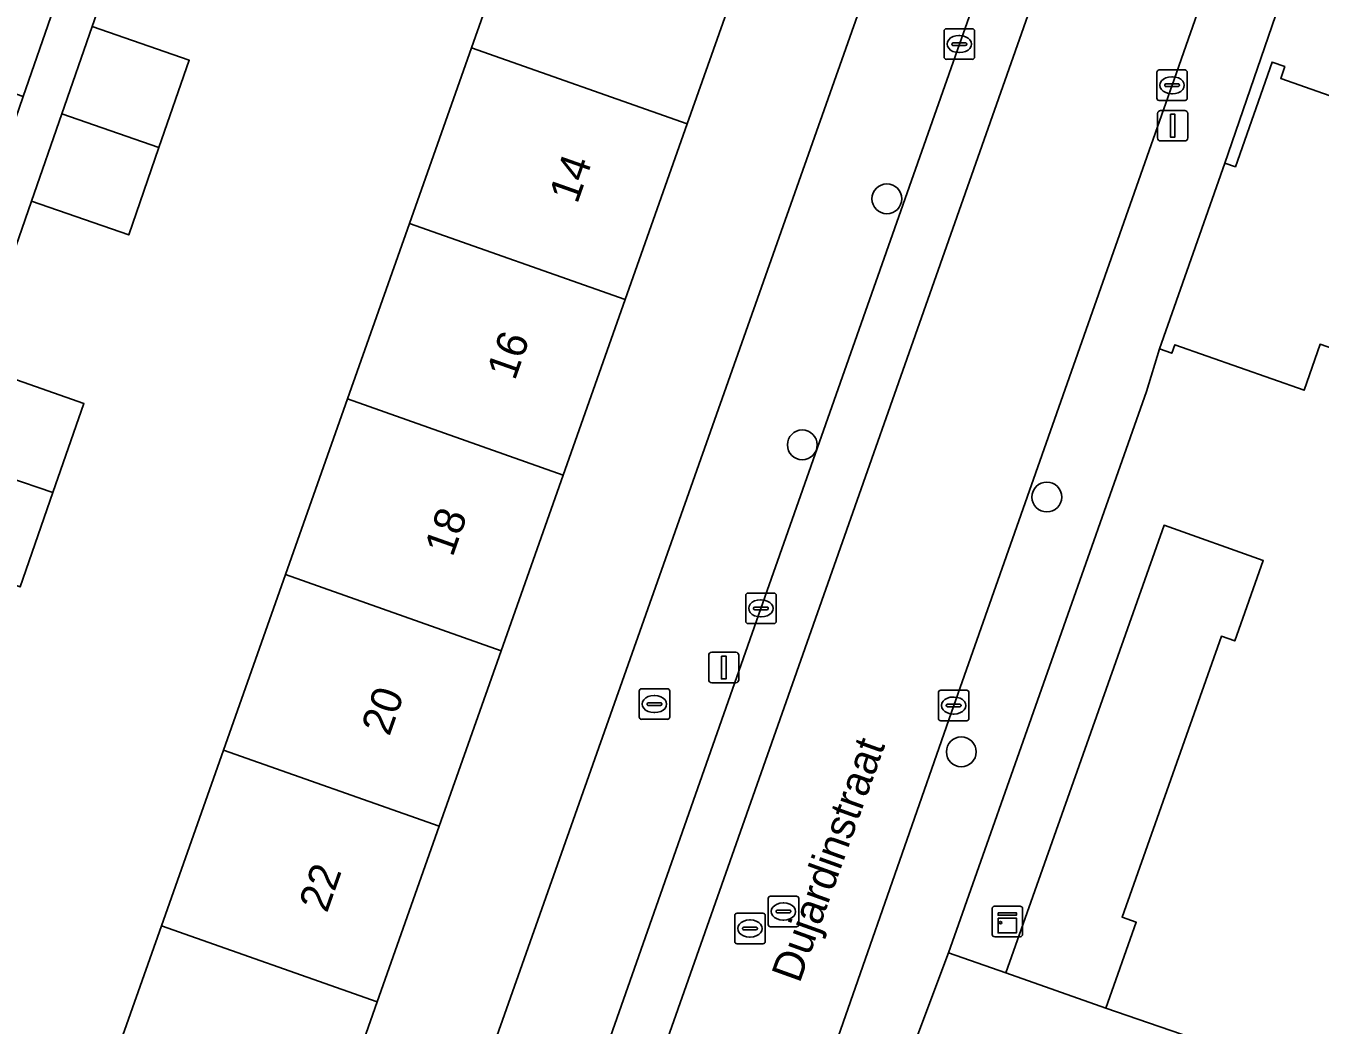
# Model space of a CAD drawing. Extents: x 163266 to 164362, y 381528 to 382286.
# Drawn here: x 163762.33 to 163804.78, y 381920.09 to 381952.84 of the extents above; entities that cross this region are included whole.
import ezdxf

# ---------------------------------------------------------------- set-up
doc = ezdxf.new("R2010")
doc.units = 0
for name, color, linetype in [('IMGEO_Boom', 7, 'Continuous'), ('IMGEO_Brandkraan', 7, 'Continuous'), ('IMGEO_Erf', 7, 'Continuous'), ('IMGEO_Kast', 7, 'Continuous'), ('IMGEO_Kolk', 7, 'Continuous'), ('IMGEO_Lichtmast', 7, 'Continuous'), ('IMGEO_Openbare_ruimte_label', 7, 'Continuous'), ('IMGEO_Pand', 7, 'Continuous'), ('IMGEO_Pand_nummerreeks', 7, 'Continuous'), ('IMGEO_Parkeervlak_open', 7, 'Continuous'), ('IMGEO_Rijbaan_lokaal_open', 7, 'Continuous'), ('IMGEO_Rioolput', 7, 'Continuous'), ('IMGEO_Voetpad_open', 7, 'Continuous')]:
    doc.layers.add(name, color=color, linetype=linetype)

msp = doc.modelspace()

# ---------------------------------------------------------------- linework, layer by layer
at = {"layer": 'IMGEO_Boom'}
for centre in [(163790.573, 381947.177), (163787.797, 381939.109), (163795.82, 381937.4), (163793.013, 381929.046)]:
    msp.add_circle(centre, 0.489, dxfattribs=at)
at = {"layer": 'IMGEO_Brandkraan'}
for p, q in [((163782.446, 381930.187), (163782.446, 381931.039)), ((163782.521, 381931.113), (163783.373, 381931.113)), ((163782.934, 381930.893), (163782.959, 381930.893)), ((163783.447, 381931.039), (163783.447, 381930.187)), ((163782.705, 381930.607), (163782.705, 381930.619)), ((163783.143, 381930.57), (163782.745, 381930.57)), ((163782.748, 381930.656), (163783.146, 381930.656)), ((163782.957, 381930.333), (163782.932, 381930.333)), ((163783.189, 381930.619), (163783.189, 381930.607)), ((163783.373, 381930.113), (163782.521, 381930.113))]:
    msp.add_line(p, q, dxfattribs=at)
for points in [[(163782.446, 381930.187), (163782.446, 381931.039)], [(163782.521, 381931.113), (163783.373, 381931.113)], [(163783.447, 381931.039), (163783.447, 381930.187)], [(163783.373, 381930.113), (163782.521, 381930.113)]]:
    msp.add_lwpolyline(points, dxfattribs=at)
for centre, radius, start, end in [((163782.523, 381931.037), 0.0765, 91.552, 178.448), ((163782.523, 381931.037), 0.0765, 91.552, 178.448), ((163783.371, 381931.037), 0.0765, 1.552, 88.448), ((163783.371, 381931.037), 0.0765, 1.552, 88.448), ((163782.745, 381930.616), 0.0403, 85.8775, 175.7526), ((163782.742, 381930.606), 0.0366, 178.938, 274.7102), ((163783.146, 381930.613), 0.043, 264.8664, 352.4533), ((163783.15, 381930.618), 0.0386, 1.7309, 96.639), ((163782.523, 381930.189), 0.0765, 181.552, 268.448), ((163782.523, 381930.189), 0.0765, 181.552, 268.448), ((163783.371, 381930.189), 0.0765, 271.552, 358.448), ((163783.371, 381930.189), 0.0765, 271.552, 358.448)]:
    msp.add_arc(centre, radius, start, end, dxfattribs=at)
for centre, major_axis, ratio, start_param, end_param in [((163782.933, 381930.613), (-0.387, 0.002), 0.722429, 4.712389, 7.853982), ((163782.958, 381930.613), (-0.39, 0.002), 0.717154, 1.570796, 4.712389)]:
    msp.add_ellipse(centre, major_axis=major_axis, ratio=ratio, start_param=start_param, end_param=end_param, dxfattribs=at)
at = {"layer": 'IMGEO_Erf'}
msp.add_lwpolyline([(163791.996, 381959.944), (163788.141, 381961.307), (163786.05, 381955.385), (163784.018, 381949.629), (163781.986, 381943.873), (163779.953, 381938.117), (163777.921, 381932.362), (163775.889, 381926.606), (163773.857, 381920.85), (163771.824, 381915.094), (163769.792, 381909.339), (163767.703, 381903.421), (163771.539, 381902.067)], close=True, dxfattribs=at)
for points in [[(163766.535, 381958.634), (163764.506, 381952.826), (163767.69, 381951.72), (163766.695, 381948.856), (163765.701, 381945.992), (163762.517, 381947.097), (163760.643, 381941.721), (163764.235, 381940.469), (163763.218, 381937.553), (163762.137, 381934.452)], [(163760.627, 381905.919), (163762.717, 381911.837), (163764.749, 381917.592), (163766.781, 381923.348), (163768.814, 381929.105), (163770.846, 381934.861), (163772.878, 381940.616), (163774.911, 381946.372), (163776.943, 381952.128), (163778.975, 381957.883)], [(163804.785, 381942.408), (163804.255, 381940.9), (163800.015, 381942.39), (163799.918, 381942.116), (163799.514, 381942.258), (163799.091, 381940.863), (163792.59, 381922.456), (163794.479, 381921.807), (163799.663, 381936.474), (163802.92, 381935.323), (163801.986, 381932.681), (163801.545, 381932.837), (163798.288, 381923.623), (163798.75, 381923.459), (163797.756, 381920.649), (163820.697, 381912.77)]]:
    msp.add_lwpolyline(points, dxfattribs=at)
at = {"layer": 'IMGEO_Kast'}
for p, q in [((163794.099, 381923.984), (163794.94, 381923.984)), ((163794.94, 381923.984), (163794.099, 381923.984)), ((163794.024, 381923.059), (163794.024, 381923.9)), ((163794.024, 381923.9), (163794.024, 381923.059)), ((163795.024, 381923.909), (163795.024, 381923.068)), ((163795.024, 381923.068), (163795.024, 381923.909)), ((163794.949, 381922.984), (163794.108, 381922.984)), ((163794.108, 381922.984), (163794.949, 381922.984))]:
    msp.add_line(p, q, dxfattribs=at)
for points in [[(163794.219, 381923.774), (163794.819, 381923.774), (163794.819, 381923.689), (163794.219, 381923.689), (163794.219, 381923.774)], [(163794.219, 381923.599), (163794.819, 381923.599), (163794.819, 381923.11), (163794.219, 381923.11), (163794.219, 381923.599)]]:
    msp.add_lwpolyline(points, dxfattribs=at)
msp.add_circle((163794.303, 381923.448), 0.0377, dxfattribs=at)
for centre, start, end in [((163794.102, 381923.906), 92.4484, 184.2845), ((163794.102, 381923.906), 92.4484, 184.2845), ((163794.946, 381923.906), 2.4484, 94.2845), ((163794.946, 381923.906), 2.4484, 94.2845), ((163794.102, 381923.062), 182.4484, 274.2845), ((163794.102, 381923.062), 182.4484, 274.2845), ((163794.946, 381923.062), 272.4484, 4.2845), ((163794.946, 381923.062), 272.4484, 4.2845)]:
    msp.add_arc(centre, 0.0779, start, end, dxfattribs=at)
at = {"layer": 'IMGEO_Kolk'}
for p, q in [((163792.448, 381951.823), (163792.448, 381952.675)), ((163792.523, 381952.749), (163793.375, 381952.749)), ((163792.936, 381952.529), (163792.961, 381952.529)), ((163793.449, 381952.675), (163793.449, 381951.823)), ((163792.707, 381952.243), (163792.707, 381952.255)), ((163793.145, 381952.206), (163792.747, 381952.206)), ((163792.75, 381952.292), (163793.148, 381952.292)), ((163792.959, 381951.969), (163792.934, 381951.969)), ((163793.191, 381952.255), (163793.191, 381952.243)), ((163793.375, 381951.749), (163792.523, 381951.749)), ((163799.426, 381950.473), (163799.426, 381951.325)), ((163799.501, 381951.399), (163800.353, 381951.399)), ((163799.914, 381951.179), (163799.939, 381951.179)), ((163800.427, 381951.325), (163800.427, 381950.473)), ((163799.685, 381950.893), (163799.685, 381950.905)), ((163800.123, 381950.856), (163799.725, 381950.856)), ((163799.728, 381950.942), (163800.126, 381950.942)), ((163800.169, 381950.905), (163800.169, 381950.893)), ((163800.353, 381950.399), (163799.501, 381950.399)), ((163799.937, 381950.619), (163799.912, 381950.619)), ((163785.94, 381933.324), (163785.94, 381934.176)), ((163786.015, 381934.25), (163786.867, 381934.25)), ((163786.941, 381934.176), (163786.941, 381933.324)), ((163786.199, 381933.744), (163786.199, 381933.756)), ((163786.637, 381933.707), (163786.239, 381933.707)), ((163786.242, 381933.793), (163786.64, 381933.793)), ((163786.428, 381934.03), (163786.453, 381934.03)), ((163786.683, 381933.756), (163786.683, 381933.744)), ((163786.451, 381933.47), (163786.426, 381933.47)), ((163786.867, 381933.25), (163786.015, 381933.25)), ((163792.263, 381930.138), (163792.263, 381930.99)), ((163792.338, 381931.064), (163793.19, 381931.064)), ((163792.751, 381930.844), (163792.776, 381930.844)), ((163793.264, 381930.99), (163793.264, 381930.138)), ((163792.522, 381930.558), (163792.522, 381930.57)), ((163792.96, 381930.521), (163792.562, 381930.521)), ((163792.565, 381930.607), (163792.963, 381930.607)), ((163793.006, 381930.57), (163793.006, 381930.558)), ((163793.19, 381930.064), (163792.338, 381930.064)), ((163792.774, 381930.284), (163792.749, 381930.284))]:
    msp.add_line(p, q, dxfattribs=at)
for points in [[(163792.448, 381951.823), (163792.448, 381952.675)], [(163792.523, 381952.749), (163793.375, 381952.749)], [(163793.449, 381952.675), (163793.449, 381951.823)], [(163793.375, 381951.749), (163792.523, 381951.749)], [(163799.426, 381950.473), (163799.426, 381951.325)], [(163799.501, 381951.399), (163800.353, 381951.399)], [(163800.427, 381951.325), (163800.427, 381950.473)], [(163800.353, 381950.399), (163799.501, 381950.399)], [(163785.94, 381933.324), (163785.94, 381934.176)], [(163786.015, 381934.25), (163786.867, 381934.25)], [(163786.941, 381934.176), (163786.941, 381933.324)], [(163786.867, 381933.25), (163786.015, 381933.25)], [(163792.263, 381930.138), (163792.263, 381930.99)], [(163792.338, 381931.064), (163793.19, 381931.064)], [(163793.264, 381930.99), (163793.264, 381930.138)], [(163793.19, 381930.064), (163792.338, 381930.064)]]:
    msp.add_lwpolyline(points, dxfattribs=at)
for centre, radius, start, end in [((163792.525, 381952.673), 0.0765, 91.552, 178.448), ((163792.525, 381952.673), 0.0765, 91.552, 178.448), ((163793.373, 381952.673), 0.0765, 1.552, 88.448), ((163793.373, 381952.673), 0.0765, 1.552, 88.448), ((163792.747, 381952.252), 0.0403, 85.8775, 175.7526), ((163792.744, 381952.242), 0.0366, 178.938, 274.7102), ((163793.148, 381952.249), 0.043, 264.8664, 352.4533), ((163793.152, 381952.254), 0.0386, 1.7309, 96.639), ((163792.525, 381951.825), 0.0765, 181.552, 268.448), ((163792.525, 381951.825), 0.0765, 181.552, 268.448), ((163793.373, 381951.825), 0.0765, 271.552, 358.448), ((163793.373, 381951.825), 0.0765, 271.552, 358.448), ((163799.503, 381951.323), 0.0765, 91.552, 178.448), ((163799.503, 381951.323), 0.0765, 91.552, 178.448), ((163800.351, 381951.323), 0.0765, 1.552, 88.448), ((163800.351, 381951.323), 0.0765, 1.552, 88.448), ((163799.725, 381950.902), 0.0403, 85.8775, 175.7526), ((163799.722, 381950.892), 0.0366, 178.938, 274.7102), ((163800.126, 381950.899), 0.043, 264.8664, 352.4533), ((163800.13, 381950.904), 0.0386, 1.7309, 96.639), ((163799.503, 381950.475), 0.0765, 181.552, 268.448), ((163799.503, 381950.475), 0.0765, 181.552, 268.448), ((163800.351, 381950.475), 0.0765, 271.552, 358.448), ((163800.351, 381950.475), 0.0765, 271.552, 358.448), ((163786.017, 381934.174), 0.0765, 91.552, 178.448), ((163786.017, 381934.174), 0.0765, 91.552, 178.448), ((163786.865, 381934.174), 0.0765, 1.552, 88.448), ((163786.865, 381934.174), 0.0765, 1.552, 88.448), ((163786.239, 381933.753), 0.0403, 85.8775, 175.7526), ((163786.236, 381933.743), 0.0366, 178.938, 274.7102), ((163786.64, 381933.75), 0.043, 264.8664, 352.4533), ((163786.644, 381933.755), 0.0386, 1.7309, 96.639), ((163786.017, 381933.326), 0.0765, 181.552, 268.448), ((163786.017, 381933.326), 0.0765, 181.552, 268.448), ((163786.865, 381933.326), 0.0765, 271.552, 358.448), ((163786.865, 381933.326), 0.0765, 271.552, 358.448), ((163792.34, 381930.988), 0.0765, 91.552, 178.448), ((163792.34, 381930.988), 0.0765, 91.552, 178.448), ((163793.188, 381930.988), 0.0765, 1.552, 88.448), ((163793.188, 381930.988), 0.0765, 1.552, 88.448), ((163792.562, 381930.567), 0.0403, 85.8775, 175.7526), ((163792.559, 381930.557), 0.0366, 178.938, 274.7102), ((163792.963, 381930.564), 0.043, 264.8664, 352.4533), ((163792.967, 381930.569), 0.0386, 1.7309, 96.639), ((163792.34, 381930.14), 0.0765, 181.552, 268.448), ((163792.34, 381930.14), 0.0765, 181.552, 268.448), ((163793.188, 381930.14), 0.0765, 271.552, 358.448), ((163793.188, 381930.14), 0.0765, 271.552, 358.448)]:
    msp.add_arc(centre, radius, start, end, dxfattribs=at)
for centre, major_axis, ratio, start_param, end_param in [((163792.935, 381952.249), (-0.387, 0.002), 0.722429, 4.712389, 7.853982), ((163792.96, 381952.249), (-0.39, 0.002), 0.717154, 1.570796, 4.712389), ((163799.913, 381950.899), (-0.387, 0.002), 0.722429, 4.712389, 7.853982), ((163799.938, 381950.899), (-0.39, 0.002), 0.717154, 1.570796, 4.712389), ((163786.427, 381933.75), (-0.387, 0.002), 0.722429, 4.712389, 7.853982), ((163786.452, 381933.75), (-0.39, 0.002), 0.717154, 1.570796, 4.712389), ((163792.75, 381930.564), (-0.387, 0.002), 0.722429, 4.712389, 7.853982), ((163792.775, 381930.564), (-0.39, 0.002), 0.717154, 1.570796, 4.712389)]:
    msp.add_ellipse(centre, major_axis=major_axis, ratio=ratio, start_param=start_param, end_param=end_param, dxfattribs=at)
at = {"layer": 'IMGEO_Lichtmast'}
for p, q in [((163799.453, 381949.173), (163799.453, 381949.973)), ((163799.453, 381949.973), (163799.453, 381949.173)), ((163799.553, 381950.073), (163800.343, 381950.073)), ((163800.343, 381950.073), (163799.553, 381950.073)), ((163800.443, 381949.973), (163800.443, 381949.173)), ((163800.443, 381949.173), (163800.443, 381949.973)), ((163800.343, 381949.073), (163799.553, 381949.073)), ((163799.553, 381949.073), (163800.343, 381949.073)), ((163784.727, 381931.411), (163784.727, 381932.211)), ((163784.727, 381932.211), (163784.727, 381931.411)), ((163784.827, 381932.311), (163785.617, 381932.311)), ((163785.617, 381932.311), (163784.827, 381932.311)), ((163785.717, 381932.211), (163785.717, 381931.411)), ((163785.717, 381931.411), (163785.717, 381932.211)), ((163785.617, 381931.311), (163784.827, 381931.311)), ((163784.827, 381931.311), (163785.617, 381931.311))]:
    msp.add_line(p, q, dxfattribs=at)
for points in [[(163799.873, 381949.948), (163800.023, 381949.948), (163800.023, 381949.198), (163799.873, 381949.198), (163799.873, 381949.948)], [(163785.147, 381932.186), (163785.297, 381932.186), (163785.297, 381931.436), (163785.147, 381931.436), (163785.147, 381932.186)]]:
    msp.add_lwpolyline(points, dxfattribs=at)
for centre, start, end in [((163799.553, 381949.973), 90, 180), ((163799.553, 381949.973), 90, 180), ((163800.343, 381949.973), 0, 90), ((163800.343, 381949.973), 360, 90), ((163799.553, 381949.173), 180, 270), ((163799.553, 381949.173), 180, 270), ((163800.343, 381949.173), 270, 0), ((163800.343, 381949.173), 270, 0), ((163784.827, 381932.211), 90, 180), ((163784.827, 381932.211), 90, 180), ((163785.617, 381932.211), 0, 90), ((163785.617, 381932.211), 360, 90), ((163784.827, 381931.411), 180, 270), ((163784.827, 381931.411), 180, 270), ((163785.617, 381931.411), 270, 0), ((163785.617, 381931.411), 270, 0)]:
    msp.add_arc(centre, 0.1, start, end, dxfattribs=at)
at = {"layer": 'IMGEO_Pand'}
for points in [[(163776.943, 381952.128), (163784.018, 381949.629), (163786.05, 381955.385), (163778.975, 381957.883)], [(163759.056, 381951.632), (163762.24, 381950.527), (163763.235, 381953.391), (163760.051, 381954.496)], [(163766.695, 381948.856), (163767.69, 381951.72), (163764.506, 381952.826), (163763.512, 381949.962)], [(163774.911, 381946.372), (163781.986, 381943.873), (163784.018, 381949.629), (163776.943, 381952.128)], [(163816.929, 381946.755), (163816.757, 381946.815), (163816.643, 381946.492), (163811.511, 381948.296), (163811.616, 381948.596), (163808.606, 381949.654), (163808.504, 381949.363), (163803.49, 381951.125), (163803.625, 381951.51), (163803.21, 381951.656), (163802.004, 381948.226), (163801.654, 381948.349), (163799.514, 381942.258), (163799.918, 381942.116), (163800.015, 381942.39), (163804.255, 381940.9), (163804.785, 381942.408), (163809.76, 381940.659), (163809.211, 381939.097), (163813.49, 381937.593), (163813.391, 381937.31), (163813.612, 381937.232)], [(163766.695, 381948.856), (163763.512, 381949.962), (163762.517, 381947.097), (163765.701, 381945.992)], [(163774.911, 381946.372), (163772.878, 381940.616), (163779.953, 381938.117), (163781.986, 381943.873)], [(163764.235, 381940.469), (163760.643, 381941.721), (163759.802, 381942.014), (163758.775, 381939.054), (163763.218, 381937.553)], [(163772.878, 381940.616), (163770.846, 381934.861), (163777.921, 381932.362), (163779.953, 381938.117)], [(163763.218, 381937.553), (163758.775, 381939.054), (163757.714, 381935.994), (163758.439, 381935.741), (163762.137, 381934.452)], [(163794.479, 381921.807), (163797.756, 381920.649), (163798.75, 381923.459), (163798.288, 381923.623), (163801.545, 381932.837), (163801.986, 381932.681), (163802.92, 381935.323), (163799.663, 381936.474)], [(163775.889, 381926.606), (163777.921, 381932.362), (163770.846, 381934.861), (163768.814, 381929.105)], [(163766.781, 381923.348), (163773.857, 381920.85), (163775.889, 381926.606), (163768.814, 381929.105)], [(163766.781, 381923.348), (163764.749, 381917.592), (163771.824, 381915.094), (163773.857, 381920.85)]]:
    msp.add_lwpolyline(points, close=True, dxfattribs=at)
at = {"layer": 'IMGEO_Parkeervlak_open'}
msp.add_lwpolyline([(163800.18, 381967.343), (163798.523, 381967.981), (163792.95, 381952.249), (163786.442, 381933.75), (163779.289, 381913.394), (163778.922, 381912.306), (163780.576, 381911.693)], close=True, dxfattribs=at)
at = {"layer": 'IMGEO_Rijbaan_lokaal_open'}
msp.add_lwpolyline([(163800.18, 381967.343), (163780.576, 381911.693), (163785.506, 381909.865), (163785.986, 381911.164), (163792.763, 381930.564), (163799.926, 381950.899), (163805.033, 381965.475)], close=True, dxfattribs=at)
at = {"layer": 'IMGEO_Rioolput'}
for p, q in [((163786.678, 381923.387), (163786.678, 381924.239)), ((163786.753, 381924.313), (163787.605, 381924.313)), ((163787.166, 381924.093), (163787.191, 381924.093)), ((163787.679, 381924.239), (163787.679, 381923.387)), ((163785.581, 381922.83), (163785.581, 381923.682)), ((163785.656, 381923.756), (163786.508, 381923.756)), ((163786.069, 381923.536), (163786.094, 381923.536)), ((163786.582, 381923.682), (163786.582, 381922.83)), ((163786.937, 381923.807), (163786.937, 381923.819)), ((163787.375, 381923.77), (163786.977, 381923.77)), ((163786.98, 381923.856), (163787.378, 381923.856)), ((163787.189, 381923.533), (163787.164, 381923.533)), ((163787.421, 381923.819), (163787.421, 381923.807)), ((163785.84, 381923.25), (163785.84, 381923.262)), ((163786.278, 381923.213), (163785.88, 381923.213)), ((163785.883, 381923.299), (163786.281, 381923.299)), ((163786.324, 381923.262), (163786.324, 381923.25)), ((163787.605, 381923.313), (163786.753, 381923.313)), ((163786.508, 381922.756), (163785.656, 381922.756)), ((163786.092, 381922.976), (163786.067, 381922.976))]:
    msp.add_line(p, q, dxfattribs=at)
for points in [[(163786.678, 381923.387), (163786.678, 381924.239)], [(163786.753, 381924.313), (163787.605, 381924.313)], [(163787.679, 381924.239), (163787.679, 381923.387)], [(163785.581, 381922.83), (163785.581, 381923.682)], [(163785.656, 381923.756), (163786.508, 381923.756)], [(163786.582, 381923.682), (163786.582, 381922.83)], [(163787.605, 381923.313), (163786.753, 381923.313)], [(163786.508, 381922.756), (163785.656, 381922.756)]]:
    msp.add_lwpolyline(points, dxfattribs=at)
for centre, radius, start, end in [((163786.755, 381924.237), 0.0765, 91.552, 178.448), ((163786.755, 381924.237), 0.0765, 91.552, 178.448), ((163787.603, 381924.237), 0.0765, 1.552, 88.448), ((163787.603, 381924.237), 0.0765, 1.552, 88.448), ((163785.658, 381923.68), 0.0765, 91.552, 178.448), ((163785.658, 381923.68), 0.0765, 91.552, 178.448), ((163786.506, 381923.68), 0.0765, 1.552, 88.448), ((163786.506, 381923.68), 0.0765, 1.552, 88.448), ((163786.977, 381923.816), 0.0403, 85.8775, 175.7526), ((163786.974, 381923.806), 0.0366, 178.938, 274.7102), ((163787.378, 381923.813), 0.043, 264.8664, 352.4533), ((163787.382, 381923.818), 0.0386, 1.7309, 96.639), ((163785.88, 381923.259), 0.0403, 85.8775, 175.7526), ((163785.877, 381923.249), 0.0366, 178.938, 274.7102), ((163786.281, 381923.256), 0.043, 264.8664, 352.4533), ((163786.285, 381923.261), 0.0386, 1.7309, 96.639), ((163786.755, 381923.389), 0.0765, 181.552, 268.448), ((163786.755, 381923.389), 0.0765, 181.552, 268.448), ((163787.603, 381923.389), 0.0765, 271.552, 358.448), ((163787.603, 381923.389), 0.0765, 271.552, 358.448), ((163785.658, 381922.832), 0.0765, 181.552, 268.448), ((163785.658, 381922.832), 0.0765, 181.552, 268.448), ((163786.506, 381922.832), 0.0765, 271.552, 358.448), ((163786.506, 381922.832), 0.0765, 271.552, 358.448)]:
    msp.add_arc(centre, radius, start, end, dxfattribs=at)
for centre, major_axis, ratio, start_param, end_param in [((163787.165, 381923.813), (-0.387, 0.002), 0.722429, 4.712389, 7.853982), ((163787.19, 381923.813), (-0.39, 0.002), 0.717154, 1.570796, 4.712389), ((163786.068, 381923.256), (-0.387, 0.002), 0.722429, 4.712389, 7.853982), ((163786.093, 381923.256), (-0.39, 0.002), 0.717154, 1.570796, 4.712389)]:
    msp.add_ellipse(centre, major_axis=major_axis, ratio=ratio, start_param=start_param, end_param=end_param, dxfattribs=at)
at = {"layer": 'IMGEO_Voetpad_open'}
for points in [[(163803.818, 381995.437), (163804.03, 381994.157), (163801.584, 381987.098), (163801.103, 381985.709), (163801.089, 381985.668), (163792.557, 381961.53), (163791.996, 381959.944), (163771.539, 381902.067), (163770.666, 381899.598), (163760.976, 381872.184), (163758.8, 381866.558)], [(163774.008, 381868.401), (163775.374, 381873.443), (163776.402, 381876.494), (163778.528, 381882.571), (163778.764, 381882.488), (163779.939, 381885.846), (163780.912, 381888.775), (163787.724, 381908.577), (163788.159, 381910.115), (163790.288, 381916.317), (163792.59, 381922.456), (163799.091, 381940.863), (163799.514, 381942.258), (163801.654, 381948.349), (163803.805, 381954.586), (163810.793, 381974.367), (163811.309, 381976.127), (163813.455, 381982.099), (163813.733, 381981.999), (163814.969, 381985.441), (163816.052, 381988.185), (163816.796, 381990.222)], [(163764.05, 381870.111), (163765.264, 381873.618), (163772.497, 381893.985), (163777.996, 381909.658), (163778.922, 381912.306), (163779.289, 381913.394), (163786.442, 381933.75), (163792.95, 381952.249), (163798.523, 381967.981), (163799.456, 381970.657), (163805.61, 381988.213), (163805.827, 381988.862)], [(163813.264, 381988.782), (163806.429, 381969.388), (163805.994, 381968.193), (163805.033, 381965.475), (163799.926, 381950.899), (163792.763, 381930.564), (163785.986, 381911.164), (163785.506, 381909.865), (163784.6, 381907.284), (163779.141, 381891.761), (163769.977, 381865.691), (163769.681, 381864.823)], [(163763.235, 381953.391), (163762.24, 381950.527), (163761.246, 381947.663), (163759.334, 381942.177), (163759.802, 381942.014), (163760.643, 381941.721), (163762.517, 381947.097), (163763.512, 381949.962), (163764.506, 381952.826), (163766.535, 381958.634)], [(163803.805, 381954.586), (163801.654, 381948.349), (163802.004, 381948.226), (163803.21, 381951.656), (163803.625, 381951.51), (163803.49, 381951.125), (163808.504, 381949.363)], [(163820.697, 381912.77), (163797.756, 381920.649), (163794.479, 381921.807), (163792.59, 381922.456), (163790.288, 381916.317), (163790.699, 381916.176), (163791.825, 381919.456), (163792.131, 381919.351), (163792.013, 381919.009), (163797.126, 381917.254), (163797.219, 381917.526), (163800.225, 381916.493), (163800.112, 381916.165), (163805.288, 381914.387)]]:
    msp.add_lwpolyline(points, dxfattribs=at)

# ---------------------------------------------------------------- texts
at = {"layer": 'IMGEO_Openbare_ruimte_label'}
msp.add_text('Dujardinstraat', height=1, rotation=70.2421, dxfattribs=at).set_placement((163787.706, 381921.434))
at = {"layer": 'IMGEO_Pand_nummerreeks'}
for s, p in [('14', (163780.411, 381946.981)), ('16', (163778.367, 381941.192)), ('18', (163776.324, 381935.407)), ('20', (163774.25, 381929.532)), ('22', (163772.204, 381923.738))]:
    msp.add_text(s, height=1, rotation=70.5532, dxfattribs=at).set_placement(p)

doc.saveas('drawing.dxf')
